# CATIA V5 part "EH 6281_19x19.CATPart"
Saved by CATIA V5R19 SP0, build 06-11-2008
Definition: EH 6281_19x19
Nomenclature: EH 6281_19x19
Description: PART--DESC
Material "Steel": density 7860 kg/m3, Young's modulus 2e+11 Pa, Poisson ratio 0.266, thermal expansion 1.17e-05 1/K
Bounding box of the stored display mesh (mm): x 157.51 to 176.49, y -101 to -82, z 20 to 39
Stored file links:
  G:\UTB\Kombinované\Bakalářská práce\Catia\FORMA\EH 6281_19x19.CATPart
  D:\Aplikace\CATIA\Nová složka\win_b64\startup\materials\Catalog.CATMaterial
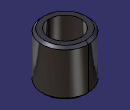
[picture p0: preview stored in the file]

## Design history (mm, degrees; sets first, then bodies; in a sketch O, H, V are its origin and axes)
Body1 "EH 6281_19x19" (main body)
  Solid1: solid without history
